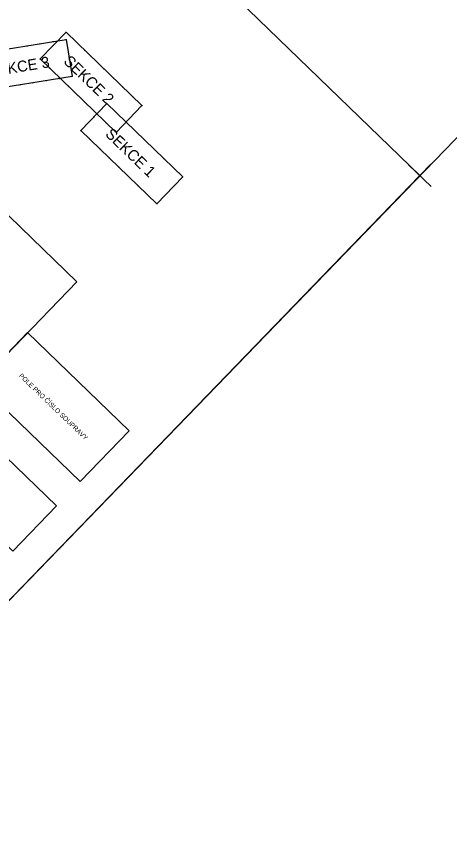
# Model space of a CAD drawing. Extents: x -819882 to -818104, y -1028540 to -1026792.
# Drawn here: x -818442 to -818304.3, y -1028536.7 to -1028272.6 of the extents above; entities that cross this region are included whole.
import ezdxf

# ---------------------------------------------------------------- set-up
doc = ezdxf.new("R2010")
doc.units = 0
for name, color, linetype in [('Rozpiska', 7, 'Continuous'), ('Rozpiska - logo SUDOP PRAHA', 7, 'Continuous'), ('Rozpiska - logo ŘSD', 7, 'Continuous'), ('Vrstva 1', 7, 'Continuous')]:
    doc.layers.add(name, color=color, linetype=linetype)

msp = doc.modelspace()

# ---------------------------------------------------------------- linework, layer by layer
at = {"layer": 'Rozpiska'}
msp.add_lwpolyline([(-818572.58, -1028317.59), (-818443.19, -1028442.73), (-818429.28, -1028428.35), (-818558.67, -1028303.22)], close=True, dxfattribs=at)
at = {"layer": 'Rozpiska - logo SUDOP PRAHA'}
for p, q in [((-818426.33, -1028277.64), (-818426.19, -1028277.5)), ((-818426.33, -1028277.5), (-818426.19, -1028277.64)), ((-818426.33, -1028277.64), (-818426.19, -1028277.5)), ((-818426.33, -1028277.5), (-818426.19, -1028277.64)), ((-818430.47, -1028280.6), (-818430.28, -1028280.57)), ((-818430.47, -1028280.6), (-818430.28, -1028280.57)), ((-818430.36, -1028280.68), (-818430.39, -1028280.48)), ((-818430.36, -1028280.68), (-818430.39, -1028280.48)), ((-818426.33, -1028279.93), (-818426.13, -1028279.89)), ((-818426.33, -1028279.93), (-818426.13, -1028279.89)), ((-818426.21, -1028280.01), (-818426.24, -1028279.81)), ((-818426.21, -1028280.01), (-818426.24, -1028279.81)), ((-818423.31, -1028280.56), (-818423.17, -1028280.42)), ((-818423.31, -1028280.42), (-818423.17, -1028280.56)), ((-818423.31, -1028280.56), (-818423.17, -1028280.42)), ((-818423.31, -1028280.42), (-818423.17, -1028280.56)), ((-818438.77, -1028281.94), (-818438.57, -1028281.91)), ((-818438.77, -1028281.94), (-818438.57, -1028281.91)), ((-818438.65, -1028282.02), (-818438.68, -1028281.82)), ((-818438.65, -1028282.02), (-818438.68, -1028281.82)), ((-818434.62, -1028281.27), (-818434.42, -1028281.24)), ((-818434.62, -1028281.27), (-818434.42, -1028281.24)), ((-818434.5, -1028281.35), (-818434.54, -1028281.15)), ((-818434.5, -1028281.35), (-818434.54, -1028281.15)), ((-818430.46, -1028281.91), (-818430.32, -1028281.77)), ((-818430.46, -1028281.77), (-818430.32, -1028281.91)), ((-818425.38, -1028285.79), (-818425.18, -1028285.76)), ((-818425.26, -1028285.87), (-818425.3, -1028285.68)), ((-818420.29, -1028283.48), (-818420.15, -1028283.34)), ((-818420.29, -1028283.34), (-818420.15, -1028283.48)), ((-818420.29, -1028283.48), (-818420.15, -1028283.34)), ((-818420.29, -1028283.34), (-818420.15, -1028283.48)), ((-818434.59, -1028286.18), (-818434.45, -1028286.04)), ((-818434.59, -1028286.04), (-818434.45, -1028286.18)), ((-818417.27, -1028286.4), (-818417.13, -1028286.26)), ((-818417.27, -1028286.26), (-818417.13, -1028286.4)), ((-818417.27, -1028286.4), (-818417.13, -1028286.26)), ((-818417.27, -1028286.26), (-818417.13, -1028286.4)), ((-818431.57, -1028289.1), (-818431.43, -1028288.96)), ((-818431.57, -1028288.96), (-818431.43, -1028289.1)), ((-818414.26, -1028289.18), (-818414.11, -1028289.32)), ((-818414.26, -1028289.18), (-818414.11, -1028289.32)), ((-818414.25, -1028289.32), (-818414.11, -1028289.18)), ((-818414.25, -1028289.32), (-818414.11, -1028289.18)), ((-818436.87, -1028293.67), (-818436.67, -1028293.63)), ((-818436.76, -1028293.75), (-818436.79, -1028293.55)), ((-818432.72, -1028293), (-818432.53, -1028292.96)), ((-818432.61, -1028293.08), (-818432.64, -1028292.88)), ((-818428.58, -1028292.32), (-818428.38, -1028292.29)), ((-818428.55, -1028292.02), (-818428.41, -1028291.88)), ((-818428.55, -1028291.88), (-818428.41, -1028292.02)), ((-818428.46, -1028292.41), (-818428.49, -1028292.21)), ((-818424.43, -1028291.65), (-818424.23, -1028291.62)), ((-818424.32, -1028291.74), (-818424.35, -1028291.54)), ((-818411.24, -1028292.1), (-818411.09, -1028292.24)), ((-818411.24, -1028292.1), (-818411.09, -1028292.24)), ((-818411.23, -1028292.24), (-818411.09, -1028292.1)), ((-818411.23, -1028292.24), (-818411.09, -1028292.1)), ((-818441.02, -1028294.34), (-818440.82, -1028294.3)), ((-818440.9, -1028294.42), (-818440.93, -1028294.22)), ((-818425.53, -1028294.94), (-818425.39, -1028294.8)), ((-818425.53, -1028294.8), (-818425.39, -1028294.94)), ((-818408.22, -1028295.02), (-818408.07, -1028295.16)), ((-818408.22, -1028295.02), (-818408.07, -1028295.16)), ((-818408.21, -1028295.16), (-818408.08, -1028295.02)), ((-818408.21, -1028295.16), (-818408.08, -1028295.02)), ((-818422.51, -1028297.86), (-818422.37, -1028297.72)), ((-818422.51, -1028297.72), (-818422.37, -1028297.86)), ((-818405.2, -1028298.08), (-818405.06, -1028297.94)), ((-818405.2, -1028297.94), (-818405.05, -1028298.08)), ((-818405.2, -1028298.08), (-818405.06, -1028297.94)), ((-818405.2, -1028297.94), (-818405.05, -1028298.08)), ((-818419.5, -1028300.64), (-818419.35, -1028300.78)), ((-818419.49, -1028300.78), (-818419.35, -1028300.64)), ((-818413.37, -1028300.36), (-818413.23, -1028300.22)), ((-818413.37, -1028300.22), (-818413.23, -1028300.36)), ((-818413.37, -1028300.36), (-818413.23, -1028300.22)), ((-818413.37, -1028300.22), (-818413.23, -1028300.36)), ((-818402.18, -1028301), (-818402.04, -1028300.86)), ((-818402.18, -1028300.86), (-818402.04, -1028301)), ((-818402.18, -1028301), (-818402.04, -1028300.86)), ((-818402.18, -1028300.86), (-818402.04, -1028301)), ((-818416.48, -1028303.56), (-818416.33, -1028303.7)), ((-818416.47, -1028303.7), (-818416.33, -1028303.56)), ((-818410.35, -1028303.28), (-818410.21, -1028303.14)), ((-818410.35, -1028303.14), (-818410.21, -1028303.28)), ((-818410.35, -1028303.28), (-818410.21, -1028303.14)), ((-818410.35, -1028303.14), (-818410.21, -1028303.28)), ((-818417.5, -1028304.63), (-818417.36, -1028304.49)), ((-818417.5, -1028304.49), (-818417.36, -1028304.63)), ((-818413.46, -1028306.48), (-818413.31, -1028306.62)), ((-818413.45, -1028306.62), (-818413.32, -1028306.48)), ((-818407.33, -1028306.2), (-818407.19, -1028306.06)), ((-818407.33, -1028306.06), (-818407.19, -1028306.2)), ((-818407.33, -1028306.2), (-818407.19, -1028306.06)), ((-818407.33, -1028306.06), (-818407.19, -1028306.2)), ((-818406.31, -1028305.27), (-818406.17, -1028305.13)), ((-818406.31, -1028305.13), (-818406.16, -1028305.27)), ((-818421.63, -1028308.9), (-818421.49, -1028308.76)), ((-818421.63, -1028308.76), (-818421.49, -1028308.9)), ((-818410.44, -1028309.54), (-818410.3, -1028309.4)), ((-818410.44, -1028309.4), (-818410.29, -1028309.54)), ((-818404.31, -1028309.12), (-818404.17, -1028308.98)), ((-818404.31, -1028308.98), (-818404.17, -1028309.12)), ((-818404.31, -1028309.12), (-818404.17, -1028308.98)), ((-818404.31, -1028308.98), (-818404.17, -1028309.12)), ((-818418.61, -1028311.82), (-818418.47, -1028311.68)), ((-818418.61, -1028311.68), (-818418.47, -1028311.82)), ((-818401.3, -1028311.9), (-818401.15, -1028312.04)), ((-818401.3, -1028311.9), (-818401.15, -1028312.04)), ((-818401.29, -1028312.04), (-818401.15, -1028311.9)), ((-818401.29, -1028312.04), (-818401.15, -1028311.9)), ((-818415.59, -1028314.74), (-818415.45, -1028314.6)), ((-818415.59, -1028314.6), (-818415.45, -1028314.74)), ((-818398.28, -1028314.82), (-818398.13, -1028314.96)), ((-818398.28, -1028314.82), (-818398.13, -1028314.96)), ((-818398.27, -1028314.96), (-818398.13, -1028314.82)), ((-818398.27, -1028314.96), (-818398.13, -1028314.82)), ((-818412.57, -1028317.66), (-818412.43, -1028317.52)), ((-818412.57, -1028317.52), (-818412.43, -1028317.66)), ((-818395.26, -1028317.74), (-818395.11, -1028317.88)), ((-818395.26, -1028317.74), (-818395.11, -1028317.88)), ((-818395.25, -1028317.88), (-818395.12, -1028317.74)), ((-818395.25, -1028317.88), (-818395.12, -1028317.74)), ((-818317.3, -1028319.76), (-818310.11, -1028326.71)), ((-818317.18, -1028326.83), (-818310.23, -1028319.64)), ((-818409.55, -1028320.58), (-818409.41, -1028320.44)), ((-818409.55, -1028320.44), (-818409.41, -1028320.58)), ((-818392.24, -1028320.8), (-818392.1, -1028320.66)), ((-818392.24, -1028320.66), (-818392.09, -1028320.8)), ((-818392.24, -1028320.8), (-818392.1, -1028320.66)), ((-818392.24, -1028320.66), (-818392.09, -1028320.8)), ((-818406.54, -1028323.36), (-818406.39, -1028323.5)), ((-818406.53, -1028323.5), (-818406.39, -1028323.36)), ((-818389.22, -1028323.72), (-818389.08, -1028323.58)), ((-818389.22, -1028323.58), (-818389.08, -1028323.72)), ((-818389.22, -1028323.72), (-818389.08, -1028323.58)), ((-818389.22, -1028323.58), (-818389.08, -1028323.72)), ((-818403.52, -1028326.28), (-818403.37, -1028326.42)), ((-818403.51, -1028326.42), (-818403.37, -1028326.28)), ((-818393.35, -1028327.99), (-818393.21, -1028327.85)), ((-818393.35, -1028327.85), (-818393.2, -1028327.99)), ((-818400.5, -1028329.2), (-818400.35, -1028329.34)), ((-818400.49, -1028329.34), (-818400.36, -1028329.2)), ((-818397.48, -1028332.26), (-818397.34, -1028332.12)), ((-818397.48, -1028332.12), (-818397.33, -1028332.26))]:
    msp.add_line(p, q, dxfattribs=at)
for points in [[(-819465.82, -1026795.83), (-818107.24, -1028109.74), (-818520.18, -1028536.72), (-819878.76, -1027222.81)], [(-818426.26, -1028277.57), (-818402.11, -1028300.93), (-818410.37, -1028309.47), (-818434.52, -1028286.11)], [(-818455.25, -1028284.6), (-818426.23, -1028279.91), (-818424.33, -1028291.64), (-818453.36, -1028296.33)], [(-818413.3, -1028300.29), (-818389.15, -1028323.65), (-818397.41, -1028332.19), (-818421.56, -1028308.83)]]:
    msp.add_lwpolyline(points, close=True, dxfattribs=at)
at = {"layer": 'Rozpiska - logo ŘSD'}
msp.add_lwpolyline([(-818671.13, -1028390.73), (-818520.18, -1028536.72), (-818313.71, -1028323.23), (-818464.66, -1028177.24)], close=True, dxfattribs=at)
at = {"layer": 'Vrstva 1'}
for points in [[(-818454.16, -1028389.35), (-818486.51, -1028358.06), (-818455.23, -1028325.72), (-818422.88, -1028357)], [(-818454.16, -1028389.35), (-818421.82, -1028420.63), (-818406.18, -1028404.46), (-818438.52, -1028373.17)]]:
    msp.add_lwpolyline(points, close=True, dxfattribs=at)

# ---------------------------------------------------------------- texts
at = {"layer": 'Rozpiska - logo SUDOP PRAHA'}
for s, rotation, p in [('SEKCE 3', 9.1828, (-818450.8, -1028291.88)), ('SEKCE 2', 315.9576, (-818427.31, -1028287.14)), ('SEKCE 1', 315.9576, (-818414.05, -1028310.31))]:
    msp.add_text(s, height=3.5, rotation=rotation, dxfattribs=at).set_placement(p)
at = {"layer": 'Vrstva 1'}
msp.add_text('POLE PRO ČÍSLO SOUPRAVY', height=1.5, rotation=315.9576, dxfattribs=at).set_placement((-818441.4, -1028387.08))

doc.saveas('drawing.dxf')
